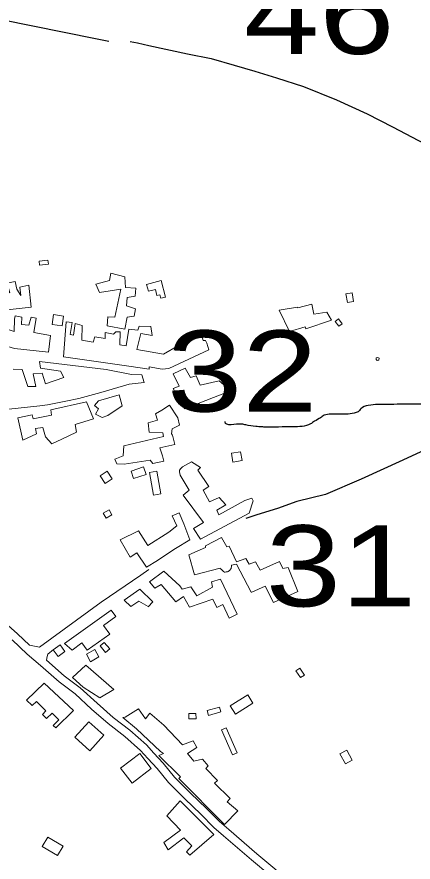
# Model space of a CAD drawing. Extents: x 476989 to 498418, y 4381813 to 4416555.
# Drawn here: x 486526 to 486771, y 4385937 to 4386458 of the extents above; entities that cross this region are included whole.
import ezdxf
from ezdxf.enums import TextEntityAlignment as Align

# ---------------------------------------------------------------- set-up
doc = ezdxf.new("R2010")
doc.units = 0
doc.header["$LTSCALE"] = 20
for name, color, linetype, lineweight in [('13', 7, 'Continuous', 13), ('36', 7, 'Continuous', 13), ('47', 7, 'Continuous', 13), ('6', 7, 'Continuous', 25)]:
    doc.layers.add(name, color=color, linetype=linetype, lineweight=lineweight)

msp = doc.modelspace()

# ---------------------------------------------------------------- linework, layer by layer
at = {"layer": '36'}
msp.add_line((486540.28, 4386069.61), (486534.08, 4386070.75), dxfattribs=at)
for points in [[(486430.77, 4386156.99), (486441.12, 4386150.75), (486448.41, 4386147.06), (486452.38, 4386144.25), (486460.67, 4386137.54), (486469.19, 4386130.45), (486480.08, 4386120.84), (486491.42, 4386111.38), (486501.38, 4386101.13), (486507.23, 4386094.96), (486514.95, 4386088.08), (486526.72, 4386077.71), (486534.08, 4386070.75)], [(486540.28, 4386069.61), (486578.34, 4386097.34), (486602.68, 4386113.89), (486607.72, 4386117.5)], [(486523.35, 4386074.02), (486532.65, 4386065.22), (486540.8, 4386058.29), (486552.33, 4386048.11), (486562.16, 4386040.73), (486572.37, 4386031.34), (486582.49, 4386022.41), (486592.8, 4386014.54), (486602.61, 4386005.83), (486606.95, 4386000.85), (486612.74, 4385994.68), (486619.79, 4385986.1), (486629.85, 4385975.99), (486639.69, 4385966.47), (486647.81, 4385958.34), (486653.82, 4385953.26), (486671.02, 4385938.29), (486693.52, 4385919.56)], [(486548.84, 4386068.05), (486545.33, 4386065.35), (486544.94, 4386063.86), (486544.6, 4386061.6)], [(486544.6, 4386061.6), (486555.49, 4386051.99), (486565.36, 4386044.57), (486575.71, 4386035.06), (486585.66, 4386026.27), (486595.98, 4386018.4), (486606.16, 4386009.36), (486610.66, 4386004.2), (486616.49, 4385997.98), (486623.5, 4385989.46), (486633.36, 4385979.55), (486643.2, 4385970.03), (486651.2, 4385962.02), (486657.07, 4385957.05), (486674.26, 4385942.1), (486696.74, 4385923.39), (486714.13, 4385908.6)]]:
    msp.add_lwpolyline(points, dxfattribs=at)
at = {"layer": '47'}
for points in [[(486545.44, 4386308.32), (486539.98, 4386307.63), (486540.29, 4386305.17), (486545.75, 4386305.86)], [(486577.27, 4386288.43), (486590.28, 4386290.5), (486586.65, 4386273.21), (486582.3, 4386273.35), (486582, 4386267.8), (486592.78, 4386265.77), (486594.38, 4386273.1), (486598.59, 4386273.79), (486599.33, 4386278.36), (486593.88, 4386280.24), (486594.33, 4386285.18), (486599.14, 4386286.09), (486599.59, 4386291.11), (486593.22, 4386291.35), (486592.79, 4386298.04), (486584.26, 4386300.19), (486583.45, 4386295.7), (486575.01, 4386293.49)], [(486534.97, 4386279.36), (486533.66, 4386292.88), (486528.09, 4386291.69), (486528.69, 4386286.43), (486526.12, 4386290.44), (486525.21, 4386295.1), (486520.32, 4386294.2), (486521.89, 4386288.17), (486517.01, 4386288.39), (486514.45, 4386293.23), (486510.91, 4386292.16), (486508.28, 4386296.77), (486499.08, 4386293.75), (486503.95, 4386277.63), (486513.67, 4386280.34), (486514.45, 4386277.1)], [(486606.3, 4386293.34), (486615.34, 4386295.69), (486617.98, 4386285.52), (486615, 4386284.77), (486614.46, 4386286.9), (486612.69, 4386286.48), (486611.82, 4386290.13), (486607.54, 4386289.11)], [(486729.2, 4386287.45), (486730.15, 4386282.12), (486734.01, 4386282.81), (486733.06, 4386288.14)], [(486720.42, 4386271.37), (486704.51, 4386265.9), (486704, 4386267.18), (486694.35, 4386264.24), (486688.09, 4386277.54), (486699.45, 4386279.4), (486699.59, 4386278.95), (486708.18, 4386281.23), (486709.36, 4386274.98), (486717.48, 4386276.14)], [(486508.93, 4386258.57), (486524.7, 4386253.84), (486545.82, 4386251.51), (486547.02, 4386261.85), (486536.69, 4386263.65), (486538.17, 4386272.63), (486535.1, 4386273.05), (486533.68, 4386268.27), (486529.19, 4386268.63), (486529.25, 4386273.21), (486525.13, 4386273.95), (486524.81, 4386271.92), (486524.55, 4386264.27), (486511.03, 4386268.75)], [(486548.78, 4386274.73), (486554.95, 4386273.85), (486554.09, 4386267.83), (486547.92, 4386268.71)], [(486722.66, 4386270.52), (486724.94, 4386267.57), (486726.91, 4386269.1), (486724.63, 4386272.05)], [(486555.01, 4386248.68), (486595.38, 4386242.93), (486607.88, 4386241.17), (486607.9, 4386242.45), (486615.98, 4386240.98), (486620.04, 4386241.52), (486644.74, 4386252.95), (486643.38, 4386257.02), (486642.65, 4386258.76), (486641.08, 4386258.85), (486639.44, 4386265.18), (486628.11, 4386260.31), (486628.83, 4386257.75), (486625.87, 4386255.77), (486616.72, 4386250.35), (486600.25, 4386253.13), (486602.72, 4386263), (486609.75, 4386261.85), (486608.86, 4386267.49), (486601.73, 4386267.67), (486600.87, 4386265.06), (486595.33, 4386265.66), (486593.75, 4386255.55), (486589.71, 4386255.99), (486589.98, 4386264.16), (486587.2, 4386264.2), (486585.83, 4386262.72), (486580.81, 4386263.69), (486580.76, 4386260.02), (486574.4, 4386260.93), (486573.38, 4386257.8), (486566.27, 4386259.02), (486566.55, 4386268.1), (486562.13, 4386269.14), (486561.28, 4386262.02), (486559.04, 4386262.43), (486560.42, 4386269.76), (486556.67, 4386270.34)], [(486749.63, 4386246.79), (486749.69, 4386247.76), (486748.9, 4386248.33), (486748, 4386247.97), (486747.81, 4386247.02), (486748.52, 4386246.35), (486749.47, 4386246.59)], [(486629.66, 4386216.55), (486655.93, 4386226.98), (486653.82, 4386231.51), (486651, 4386233.95), (486639.25, 4386231.19), (486636.93, 4386236.93), (486633.32, 4386235.85), (486630.1, 4386241.75), (486622.69, 4386238.11), (486626.41, 4386230.55), (486622.72, 4386229.18)], [(486591.12, 4386218.52), (486582.33, 4386212.5), (486578.94, 4386211.34), (486574.84, 4386213.28), (486576.54, 4386216.63), (486574.17, 4386218.62), (486576.53, 4386221.51), (486589.27, 4386225.15)], [(486573.53, 4386210.52), (486569.25, 4386220.86), (486547.12, 4386216), (486547.59, 4386212.62), (486536.38, 4386210.53), (486535.74, 4386212.94), (486526.86, 4386211.04), (486529.89, 4386197.27), (486538.35, 4386201.2), (486537.8, 4386204.51), (486542.16, 4386205.04), (486543.88, 4386199.39), (486547.87, 4386194.98), (486554.06, 4386197.82), (486563.05, 4386202.27), (486562.14, 4386207.01)], [(486620.31, 4386218.78), (486625.46, 4386210.98), (486626.67, 4386206.61), (486622.06, 4386204.35), (486621.71, 4386201.13), (486622.23, 4386200.37), (486623.65, 4386194.65), (486614.54, 4386192.45), (486616.04, 4386187.55), (486616.9, 4386184.39), (486610.12, 4386182.83), (486608.5, 4386185.03), (486592.41, 4386182.41), (486587.83, 4386182.63), (486586.6, 4386185.5), (486591.73, 4386187.68), (486592.27, 4386193.82), (486616.67, 4386199.62), (486616.32, 4386201.88), (486607.92, 4386202.3), (486607.18, 4386207.86), (486613.06, 4386209.66), (486611.76, 4386213.5), (486615.7, 4386215.85)], [(486658.69, 4386189.19), (486664.28, 4386190.09), (486665.15, 4386184.67), (486659.56, 4386183.77)], [(486639.54, 4386136.19), (486669.64, 4386152.19), (486671.92, 4386159.89), (486671.12, 4386161.55), (486666.97, 4386159.96), (486650.79, 4386151.19), (486649.63, 4386154.13), (486655.15, 4386157.28), (486651.09, 4386161.84), (486645.05, 4386159.3), (486641.1, 4386166.33), (486644.73, 4386168.61), (486637.9, 4386178.76), (486639.5, 4386180.39), (486633.92, 4386183.92), (486628.33, 4386180.77), (486627.41, 4386179.74), (486626.65, 4386178.77), (486626.48, 4386177.72), (486626.9, 4386175.77), (486632.62, 4386166.45), (486628.75, 4386163.43), (486641.42, 4386146.44), (486635.21, 4386142.86)], [(486581.99, 4386178.13), (486585.08, 4386173.38), (486580.76, 4386170.57), (486577.67, 4386175.32)], [(486605.97, 4386176.14), (486598.29, 4386173.53), (486596.7, 4386178.22), (486604.38, 4386180.83)], [(486612.68, 4386178.07), (486615.04, 4386164.08), (486610.52, 4386163.32), (486608.16, 4386177.31)], [(486583.15, 4386154.33), (486579.52, 4386152.22), (486581.28, 4386149.18), (486584.91, 4386151.29)], [(486633.01, 4386135.83), (486624.15, 4386130.41), (486616.35, 4386125.27), (486613.02, 4386122.99), (486606.2, 4386118.88), (486600.18, 4386127.67), (486596.16, 4386125.18), (486589.94, 4386135.85), (486601.35, 4386141.31), (486606.99, 4386132.23), (486619.95, 4386140.6), (486624.95, 4386144.35), (486622.04, 4386150.55), (486626.42, 4386152.44), (486629.17, 4386145.72)], [(486635.92, 4386114.11), (486632.35, 4386126.61), (486642.7, 4386131.12), (486642.71, 4386132.09), (486652.46, 4386137.28), (486655.68, 4386131.38), (486657.26, 4386131.81), (486661.78, 4386122.29), (486667.59, 4386124.31), (486669.49, 4386120.83), (486673.48, 4386122.2), (486676.26, 4386117.13), (486688.19, 4386122.51), (486690.38, 4386118.13), (486693.62, 4386118.68), (486699.48, 4386103.97), (486684.6, 4386097.05), (486679.42, 4386107.18), (486671.19, 4386103.47), (486670.74, 4386103.4), (486661.83, 4386120.71), (486658.6, 4386120.16), (486658.59, 4386119.48), (486658.42, 4386118.14), (486657.35, 4386116.88), (486656.67, 4386116.28), (486656.21, 4386116.07), (486655.46, 4386116), (486654.71, 4386115.94), (486654.56, 4386115.94), (486654.26, 4386115.94), (486653.74, 4386116.25), (486652.4, 4386117.4), (486651.74, 4386118.16), (486651.67, 4386118.23)], [(486555.7, 4386071.81), (486584.44, 4386092.48), (486587.35, 4386088.42), (486579.66, 4386082.9), (486583.5, 4386077.54), (486569.67, 4386067.63), (486566.37, 4386072.21), (486560.26, 4386067.81)], [(486548.67, 4386067.93), (486552.86, 4386071.02), (486555.93, 4386066.85), (486551.74, 4386063.76)], [(486577.59, 4386070.37), (486580.98, 4386066.31), (486583.57, 4386068.48), (486580.18, 4386072.54)], [(486569.12, 4386065.16), (486574.32, 4386068.1), (486576.9, 4386063.55), (486571.7, 4386060.61)], [(486560.51, 4386050.81), (486567.17, 4386044.86), (486577.51, 4386038.26), (486585.99, 4386043.54), (486568.8, 4386058.57)], [(486698.41, 4386054.98), (486701.23, 4386050.76), (486703.62, 4386052.36), (486700.8, 4386056.58)], [(486543.12, 4386047.38), (486561.19, 4386030.46), (486550.21, 4386019.75), (486548.67, 4386021.32), (486552.09, 4386024.67), (486547.97, 4386028.86), (486544.58, 4386025.54), (486542.04, 4386028.12), (486544.15, 4386030.21), (486538.27, 4386036.14), (486535.64, 4386033.54), (486532.25, 4386036.96)], [(486668.63, 4386040.1), (486657.82, 4386033.29), (486661.03, 4386028.2), (486671.84, 4386035.01)], [(486651.34, 4386032.55), (486643.62, 4386030.41), (486644.44, 4386027.47), (486652.16, 4386029.61)], [(486591.52, 4386026.2), (486600.05, 4386019.17), (486614.93, 4386005.23), (486616.71, 4386004), (486613.92, 4386002.69), (486627.24, 4385989.59), (486626.1, 4385988.64), (486654.43, 4385960.24), (486662.65, 4385968.68), (486655.91, 4385974.25), (486657.81, 4385976.25), (486648.27, 4385985.69), (486650.01, 4385987.24), (486642.84, 4385994.77), (486644.29, 4385996.4), (486640.67, 4386000.43), (486635.48, 4385999.16), (486631.5, 4386004.02), (486637.17, 4386007.61), (486634.91, 4386011.85), (486628.49, 4386009.24), (486616.81, 4386021.48), (486608.36, 4386028.88), (486605.61, 4386025.4), (486601.2, 4386031.54), (486593.1, 4386026.4)], [(486632.4, 4386025.31), (486636.84, 4386025.46), (486636.73, 4386028.7), (486632.29, 4386028.55)], [(486562.08, 4386014.01), (486570.73, 4386023.48), (486579.81, 4386015.19), (486571.16, 4386005.72)], [(486655.43, 4386019.81), (486662.14, 4386004.35), (486659.25, 4386003.09), (486652.54, 4386018.55)], [(486725.59, 4386003.79), (486728.98, 4385997.54), (486733.11, 4385999.78), (486729.72, 4386006.03)], [(486597.39, 4385985.67), (486609.18, 4385994.76), (486602.01, 4386004.06), (486590.22, 4385994.97)], [(486626.95, 4385974.74), (486637.82, 4385963.78), (486647.81, 4385954.11), (486633, 4385941.34), (486630.93, 4385943.39), (486634.28, 4385947.1), (486629.25, 4385952.05), (486619.61, 4385944.53), (486616.83, 4385949), (486627.14, 4385956.73), (486618.71, 4385965.48)], [(486541.9, 4385946.55), (486551.35, 4385940.96), (486554.81, 4385946.81), (486545.36, 4385952.4)]]:
    msp.add_lwpolyline(points, close=True, dxfattribs=at)
for points in [[(486524.06, 4386241.02), (486529.46, 4386240.94), (486532.92, 4386230.46), (486537.94, 4386230.32), (486536.4, 4386238.22), (486541.89, 4386238.66), (486543.82, 4386232.03), (486555.28, 4386236), (486553.09, 4386239.93), (486540.81, 4386241.76), (486540.26, 4386245.74), (486581.24, 4386240.88), (486597.03, 4386237.8), (486603.25, 4386237.63), (486604.69, 4386232.89), (486595.51, 4386231.74), (486578.03, 4386226.59), (486564.4, 4386222.96), (486556.5, 4386221.35), (486545.13, 4386219.11), (486540.4, 4386218.43), (486513.57, 4386215.51)], [(486608.02, 4386109.78), (486616.82, 4386116.48), (486626.82, 4386107.48), (486628.29, 4386105.36), (486633.64, 4386106.71), (486637.31, 4386101.18), (486647, 4386106.67), (486646.29, 4386109.83), (486651.87, 4386111.48)], [(486651.87, 4386111.48), (486662.22, 4386089.94), (486657.25, 4386087.56), (486653.28, 4386095.83), (486649.54, 4386094.05), (486647.08, 4386099.21)], [(486592.48, 4386098.6), (486602.03, 4386105.44), (486610.17, 4386097.44), (486607.2, 4386094.48)], [(486608.02, 4386109.78), (486611.27, 4386105.91), (486615.36, 4386108.32), (486624.36, 4386097.46), (486628.98, 4386100.92), (486632.79, 4386094.27), (486647.14, 4386099.1)], [(486607.29, 4386094.56), (486601.4, 4386097.87), (486596.55, 4386094.64), (486592.54, 4386098.64)]]:
    msp.add_lwpolyline(points, dxfattribs=at)
at = {"layer": '6'}
msp.add_line((486596.06, 4386443.29), (486600.64, 4386442.39), dxfattribs=at)
for points in [[(486446.35, 4386474.47), (486516.68, 4386456.82), (486574.68, 4386445.04), (486582.92, 4386443.32)], [(486600.64, 4386442.39), (486607.65, 4386440.65), (486631.5, 4386435.51), (486646.21, 4386432.66), (486660.23, 4386428.62), (486673.01, 4386424.84), (486686.48, 4386420.88), (486703.03, 4386415.38), (486723.45, 4386407.12), (486742.44, 4386398.57), (486757.96, 4386390.6), (486777.87, 4386380.02), (486798.8, 4386367.44), (486813.03, 4386356.38), (486824.46, 4386346.9), (486830.71, 4386342.04)], [(487006.7, 4386322.35), (486996.11, 4386314.49), (486969.28, 4386295.81), (486921.9, 4386259.34), (486914.05, 4386253.61), (486904.73, 4386249.79), (486884.67, 4386239.67), (486850.72, 4386224), (486803, 4386202.78), (486764.38, 4386184.86), (486738.63, 4386173.19), (486716.6, 4386163.81), (486698.96, 4386159.51), (486686.97, 4386155.06), (486674.32, 4386151.21), (486667.46, 4386148.9)]]:
    msp.add_lwpolyline(points, dxfattribs=at)
msp.add_spline([(486900.82, 4386267.12), (486890.15, 4386260.84), (486872.56, 4386253.58), (486847.29, 4386239.24), (486824.78, 4386228.53), (486811.05, 4386223.55), (486801.02, 4386219.94), (486788.56, 4386219.37), (486770.77, 4386219.55), (486762.82, 4386219.44), (486754.86, 4386219.33), (486743.07, 4386218.67), (486738.39, 4386216.56), (486736.71, 4386214.79), (486734.3, 4386213.92), (486729.34, 4386213.24), (486727.91, 4386213.26), (486723.04, 4386213.33), (486719.96, 4386213.3), (486715.82, 4386212.61), (486713.55, 4386211.14), (486709.92, 4386208.94), (486707.34, 4386207.25), (486696.59, 4386205.53), (486687.66, 4386205.36), (486680, 4386205.32), (486677.23, 4386205.43), (486673.7, 4386205.71), (486667.41, 4386206.63), (486664.95, 4386207.19), (486654.69, 4386208.68), (486654.69, 4386208.76)], degree=3, dxfattribs=at)

# ---------------------------------------------------------------- texts
at = {"layer": '13', "width": 1.25}
for s, p in [('46', (486712.75, 4386435.52)), ('32', (486665.3, 4386214.92)), ('31', (486726.21, 4386094.74))]:
    msp.add_text(s, height=50, dxfattribs=at).set_placement(p, align=Align.CENTER)

doc.saveas('drawing.dxf')
